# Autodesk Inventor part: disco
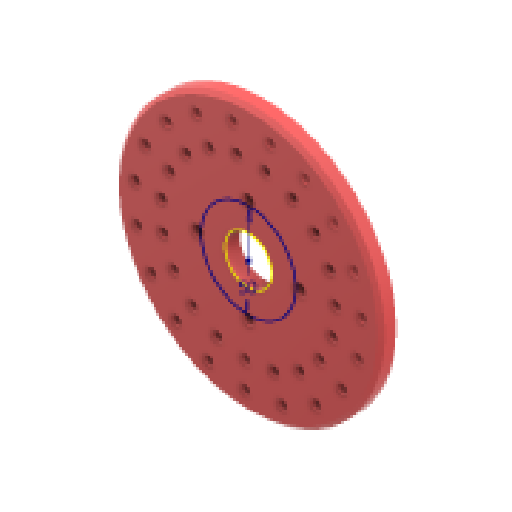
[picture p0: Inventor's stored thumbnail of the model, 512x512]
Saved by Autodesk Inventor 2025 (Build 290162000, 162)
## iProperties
Created: 2025-03
Part Number: disco
Material: Plastica ABS
Document SubType Name: Modeling
Designer: R5800u
Density: 1.06 g/cm^3
Appearance: Liscia - Rosso
Author: R5800u
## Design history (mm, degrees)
sketch "Schizzo1"
  geometry: C1 r 70 at (0, 0); C2 r 12.5 at (0, 0); 1 further point
  constraints: 2 centre point, 2 coincident
  dimensions: "d0" = 140 diameter of C1; "d1" = 25 diameter of C2
extrude "Estrusione1" new body sketch "Schizzo1" distance "d2" = 8; taper "d3" = 0 deg
sketch "Schizzo2"
  geometry: C1 r 3 at (1.5, -60) reference; C2 r 3 at (1.5, -46) reference; 1 further point
hole "Foro1" sketch "Schizzo2" at (1.5, -60), (1.5, -46) diameter "d4" = 5.3; stored, may be unused: countersink angle "d8" = 90 deg, drill point angle "d10" = 118 deg; dims "d5" = 6, "d6" = 12.6, "d7" = 2, "d9" = 4
sketch "Schizzo3"
  geometry: C1 r 12.5 at (0, 0) reference; C2 r 25 at (0, 0); 1 further point
  constraints: 1 centre point, 1 coincident
  dimensions: "d14" = 50 diameter of C2
chamfer "Smusso1" distance "d15" = 2; stored, may be unused: second distance "d16" = 2, angle "d17" = 45 deg
sketch "Schizzo4"
  geometry: C1 r 3.2 at (0, -27) reference; C2 r 3.2 at (27, 0) reference; C3 r 3.2 at (0, 27) reference; C4 r 3.2 at (-27, 0) reference; 1 further point
hole "Foro2" sketch "Schizzo4" at (0, -27), (27, 0), (0, 27), (-27, 0) diameter "d18" = 6.4; stored, may be unused: countersink angle "d22" = 90 deg, drill point angle "d24" = 118 deg; dims "d19" = 6, "d20" = 4, "d21" = 2, "d23" = 8
node "Solido1"
pattern_circular "Serie circolare1" dims angle "d12" = 360 deg
node "Riferimento1"
node "Riferimento2"
node "Riferimento3"
node "Riferimento4"
node "Riferimento5"
node "Riferimento6"
